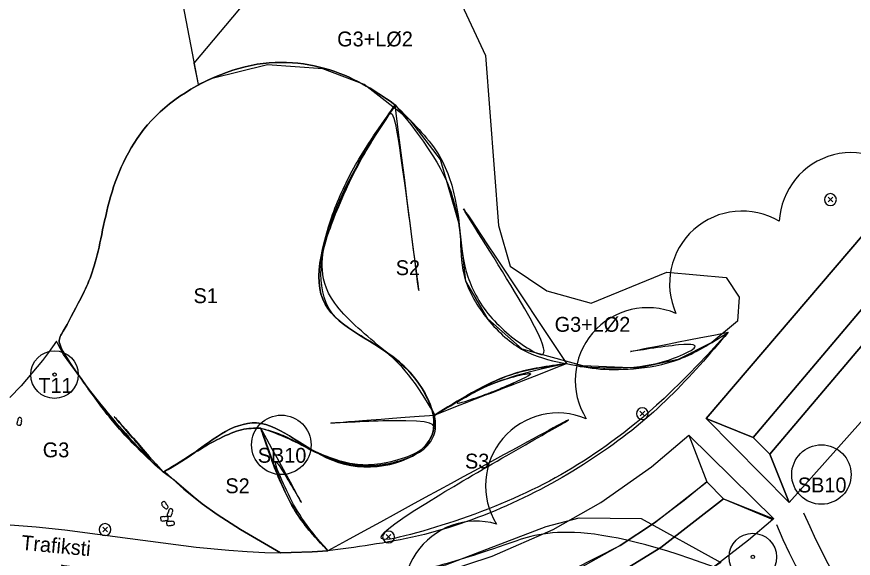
# Model space of a CAD drawing. Extents: x 0 to 512122, y 0 to 6212554.
# Drawn here: x 511431.1 to 511501.5, y 6211460.8 to 6211506.3 of the extents above; entities that cross this region are included whole.
import ezdxf

# ---------------------------------------------------------------- set-up
doc = ezdxf.new("R2010")
doc.units = 0
for name, color, linetype in [('_color plan_G3', 7, 'Continuous'), ('_lights', 7, 'Continuous'), ('_Marksten', 7, 'Continuous'), ('_Paths', 7, 'Continuous'), ('_S1_rabarber', 7, 'Continuous'), ('_S2_skovjorbær', 7, 'Continuous'), ('_S3_Mynte', 7, 'Continuous'), ('_Spredmingskorridor', 7, 'Continuous'), ('_Spredmingskorridor_hatch', 7, 'Continuous'), ('Clouds', 7, 'Continuous'), ('L40 jord udlagt muld og grøft', 7, 'Continuous'), ('Skel', 7, 'Continuous'), ('TV_U_AFM_Symbl_Gul', 7, 'Continuous'), ('TV_U_LYS_Mastenummer', 7, 'Continuous'), ('TV_U_LYS_Nyx330-Trafiksti-x2', 7, 'Continuous')]:
    doc.layers.add(name, color=color, linetype=linetype)

# ---------------------------------------------------------------- blocks, each defined once
blk = doc.blocks.new('SOLITAIRE TREES')
at = {"layer": 'Skel'}
for radius in [2, 0.141]:
    blk.add_circle((0, 0), radius, dxfattribs=at)

msp = doc.modelspace()

# ---------------------------------------------------------------- linework, layer by layer
at = {"layer": '_color plan_G3'}
msp.add_line((511446.415, 6211500.583), (511427.307, 6211601.517), dxfattribs=at)
at = {"layer": '_lights'}
for p, q in [((511499.408, 6211491.119), (511499.802, 6211490.725)), ((511499.806, 6211491.123), (511499.412, 6211490.729)), ((511483.575, 6211473.122), (511483.97, 6211472.728)), ((511483.973, 6211473.126), (511483.579, 6211472.732)), ((511438.364, 6211463.381), (511438.758, 6211462.987)), ((511438.762, 6211463.385), (511438.368, 6211462.991)), ((511462.223, 6211462.758), (511462.617, 6211462.363)), ((511462.621, 6211462.761), (511462.227, 6211462.367))]:
    msp.add_line(p, q, dxfattribs=at)
for centre, start, end in [((511499.605, 6211490.922), 315.56363, 315), ((511499.605, 6211490.922), 315, 315.56363), ((511483.772, 6211472.925), 315.56363, 315), ((511483.772, 6211472.925), 315, 315.56363), ((511438.561, 6211463.184), 315.56363, 315), ((511438.561, 6211463.184), 315, 315.56363), ((511462.42, 6211462.56), 315.56363, 315), ((511462.42, 6211462.56), 315, 315.56363)]:
    msp.add_arc(centre, 0.5, start, end, dxfattribs=at)
at = {"layer": '_Marksten'}
for points in [[(511431.425, 6211471.939), (511431.485, 6211472.018), (511431.516, 6211472.07), (511431.515, 6211472.155), (511431.534, 6211472.217), (511431.552, 6211472.28), (511431.531, 6211472.321), (511431.539, 6211472.366), (511431.55, 6211472.427), (511431.542, 6211472.483), (511431.514, 6211472.558), (511431.486, 6211472.577), (511431.458, 6211472.584), (511431.415, 6211472.594), (511431.34, 6211472.597), (511431.295, 6211472.576), (511431.272, 6211472.55), (511431.244, 6211472.505), (511431.219, 6211472.438), (511431.215, 6211472.362), (511431.202, 6211472.286), (511431.16, 6211472.229), (511431.164, 6211472.167), (511431.149, 6211472.121), (511431.144, 6211472.081), (511431.152, 6211472.002), (511431.186, 6211471.973), (511431.269, 6211471.951), (511431.33, 6211471.965)], [(511443.308, 6211465.398), (511443.325, 6211465.3), (511443.341, 6211465.242), (511443.404, 6211465.185), (511443.437, 6211465.129), (511443.47, 6211465.073), (511443.515, 6211465.06), (511443.542, 6211465.023), (511443.58, 6211464.974), (511443.626, 6211464.942), (511443.699, 6211464.91), (511443.733, 6211464.917), (511443.757, 6211464.933), (511443.793, 6211464.958), (511443.847, 6211465.012), (511443.862, 6211465.058), (511443.859, 6211465.092), (511443.845, 6211465.144), (511443.813, 6211465.207), (511443.761, 6211465.263), (511443.713, 6211465.324), (511443.701, 6211465.393), (511443.653, 6211465.433), (511443.63, 6211465.475), (511443.604, 6211465.507), (511443.541, 6211465.554), (511443.496, 6211465.549), (511443.423, 6211465.503), (511443.392, 6211465.449)], [(511444.052, 6211464.277), (511444.124, 6211464.346), (511444.163, 6211464.392), (511444.176, 6211464.476), (511444.204, 6211464.535), (511444.232, 6211464.593), (511444.218, 6211464.637), (511444.233, 6211464.68), (511444.253, 6211464.739), (511444.254, 6211464.795), (511444.239, 6211464.874), (511444.214, 6211464.898), (511444.188, 6211464.909), (511444.147, 6211464.925), (511444.073, 6211464.94), (511444.025, 6211464.927), (511443.999, 6211464.905), (511443.964, 6211464.865), (511443.929, 6211464.803), (511443.912, 6211464.728), (511443.888, 6211464.655), (511443.837, 6211464.606), (511443.83, 6211464.544), (511443.809, 6211464.501), (511443.797, 6211464.462), (511443.793, 6211464.383), (511443.822, 6211464.349), (511443.9, 6211464.314), (511443.963, 6211464.319)], [(511443.243, 6211463.95), (511443.335, 6211463.912), (511443.393, 6211463.895), (511443.475, 6211463.918), (511443.54, 6211463.916), (511443.605, 6211463.914), (511443.639, 6211463.945), (511443.685, 6211463.949), (511443.747, 6211463.954), (511443.799, 6211463.975), (511443.864, 6211464.021), (511443.876, 6211464.053), (511443.876, 6211464.082), (511443.874, 6211464.126), (511443.858, 6211464.2), (511443.826, 6211464.238), (511443.796, 6211464.253), (511443.745, 6211464.269), (511443.674, 6211464.276), (511443.599, 6211464.261), (511443.522, 6211464.254), (511443.457, 6211464.28), (511443.397, 6211464.261), (511443.35, 6211464.264), (511443.309, 6211464.258), (511443.235, 6211464.231), (511443.216, 6211464.19), (511443.216, 6211464.104), (511443.245, 6211464.049)], [(511443.762, 6211463.547), (511443.854, 6211463.509), (511443.912, 6211463.493), (511443.994, 6211463.515), (511444.059, 6211463.513), (511444.124, 6211463.511), (511444.158, 6211463.542), (511444.204, 6211463.546), (511444.266, 6211463.551), (511444.317, 6211463.573), (511444.383, 6211463.618), (511444.395, 6211463.65), (511444.394, 6211463.679), (511444.393, 6211463.723), (511444.376, 6211463.797), (511444.345, 6211463.835), (511444.314, 6211463.85), (511444.264, 6211463.866), (511444.193, 6211463.873), (511444.118, 6211463.858), (511444.041, 6211463.851), (511443.976, 6211463.878), (511443.916, 6211463.858), (511443.868, 6211463.861), (511443.828, 6211463.855), (511443.754, 6211463.828), (511443.734, 6211463.787), (511443.734, 6211463.701), (511443.764, 6211463.646)]]:
    msp.add_lwpolyline(points, close=True, dxfattribs=at)
at = {"layer": '_Paths'}
for points in [[(511619.187, 6211386.799), (511596.582, 6211393.479), (511585.389, 6211391.465), (511574.074, 6211393.08), (511564.353, 6211396.519), (511555.151, 6211400.37), (511543.395, 6211408.318), (511538.005, 6211417.069), (511534.527, 6211422.707), (511527.544, 6211428.597), (511520.899, 6211430.592), (511516.505, 6211433.059), (511513.01, 6211439.693), (511510.466, 6211444.112), (511507.781, 6211450.658), (511503.375, 6211454.994), (511500.203, 6211458.077), (511497.377, 6211464.569)], [(511614.911, 6211385.469), (511596.457, 6211390.915), (511585.439, 6211388.932), (511573.475, 6211390.64), (511563.453, 6211394.185), (511553.957, 6211398.16), (511541.549, 6211406.549), (511535.876, 6211415.757), (511532.609, 6211421.054), (511526.328, 6211426.352), (511519.916, 6211428.277), (511514.638, 6211431.24), (511510.82, 6211438.486), (511508.216, 6211443.009), (511505.662, 6211449.236), (511501.627, 6211453.206), (511498.108, 6211456.628), (511495.085, 6211463.571)]]:
    msp.add_open_spline(points, degree=3, dxfattribs=at)
at = {"layer": '_S1_rabarber'}
for points in [[(511462.989, 6211498.863), (511462.226, 6211499.418), (511458.709, 6211501.978), (511451.023, 6211503.141), (511442.323, 6211498.657), (511438.859, 6211491.961), (511437.944, 6211485.398), (511436.297, 6211482.152), (511434.723, 6211479.243), (511434.406, 6211478.815), (511436.593, 6211475.794)], [(511436.593, 6211475.794), (511434.406, 6211478.815), (511434.723, 6211479.243), (511436.297, 6211482.152), (511437.944, 6211485.398), (511438.859, 6211491.961), (511442.323, 6211498.657), (511451.023, 6211503.141), (511458.709, 6211501.978), (511462.226, 6211499.418), (511462.989, 6211498.863)], [(511443.449, 6211468.006), (511443.449, 6211468.006), (511445.663, 6211469.104), (511451.623, 6211474.122), (511458.055, 6211467.003), (511468.472, 6211469.925), (511463.799, 6211478.409), (511454.778, 6211481.205), (511458.363, 6211492.059), (511461.578, 6211496.788), (511462.989, 6211498.863)], [(511462.989, 6211498.863), (511461.578, 6211496.788), (511458.363, 6211492.059), (511454.778, 6211481.205), (511463.799, 6211478.409), (511468.472, 6211469.925), (511458.055, 6211467.003), (511451.623, 6211474.122), (511445.663, 6211469.104), (511443.449, 6211468.006), (511443.449, 6211468.006)], [(511436.593, 6211475.794), (511438.287, 6211473.464), (511441.968, 6211469.374), (511443.449, 6211468.006), (511436.593, 6211475.794), (511443.449, 6211468.006)], [(511443.449, 6211468.006), (511442.951, 6211468.457), (511441.095, 6211470.142), (511438.759, 6211472.727), (511437.147, 6211475.01), (511436.593, 6211475.794)]]:
    msp.add_open_spline(points, degree=3, dxfattribs=at)
at = {"layer": '_S2_skovjorbær'}
for points in [[(511443.578, 6211468.079), (511443.57, 6211468.074), (511445.195, 6211466.578), (511446.733, 6211465.339), (511447.983, 6211464.452), (511449.971, 6211463.191), (511453.338, 6211461.235), (511454.22, 6211461.241), (511455.977, 6211461.303), (511457.321, 6211461.397)], [(511457.321, 6211461.397), (511455.977, 6211461.303), (511454.22, 6211461.241), (511453.338, 6211461.235), (511449.971, 6211463.191), (511447.983, 6211464.452), (511446.733, 6211465.339), (511445.195, 6211466.578), (511443.57, 6211468.074), (511443.578, 6211468.079)]]:
    msp.add_lwpolyline(points, dxfattribs=at)
for points in [[(511466.301, 6211472.812), (511465.762, 6211474.059), (511464.786, 6211476.319), (511461.154, 6211478.953), (511457.036, 6211481.082), (511456.51, 6211485.204), (511457.34, 6211489.031), (511459.296, 6211493.505), (511461.652, 6211497.023), (511462.874, 6211498.746), (511462.968, 6211498.879)], [(511466.301, 6211472.812), (511464.386, 6211476.297), (511461.887, 6211478.346), (511457.205, 6211482.346), (511456.683, 6211485.477), (511457.088, 6211487.686), (511459.532, 6211493.557), (511462.685, 6211498.479), (511462.968, 6211498.879), (511466.301, 6211472.812), (511462.968, 6211498.879)], [(511466.301, 6211472.812), (511464.386, 6211476.297), (511461.887, 6211478.346), (511457.205, 6211482.346), (511456.683, 6211485.477), (511457.088, 6211487.686), (511459.532, 6211493.557), (511462.685, 6211498.479), (511462.968, 6211498.879), (511466.301, 6211472.812), (511462.968, 6211498.879)], [(511462.968, 6211498.879), (511466.855, 6211494.198), (511468.209, 6211490.046), (511468.441, 6211487.962), (511468.81, 6211484.464), (511470.824, 6211480.823), (511474.7, 6211477.831), (511477.381, 6211477.13), (511462.968, 6211498.879), (511477.381, 6211477.13)], [(511462.968, 6211498.879), (511466.855, 6211494.198), (511468.209, 6211490.046), (511468.441, 6211487.962), (511468.81, 6211484.464), (511470.824, 6211480.823), (511474.7, 6211477.831), (511477.381, 6211477.13), (511462.968, 6211498.879), (511477.381, 6211477.13)], [(511462.968, 6211498.879), (511464.432, 6211497.426), (511466.948, 6211494.929), (511468.175, 6211490.796), (511468.515, 6211487.502), (511468.519, 6211484.168), (511470.796, 6211480.478), (511473.933, 6211477.808), (511476.466, 6211477.31), (511477.381, 6211477.13)], [(511477.381, 6211477.13), (511472.658, 6211476.176), (511469.237, 6211474.575), (511466.301, 6211472.812), (511477.381, 6211477.13), (511466.301, 6211472.812)], [(511477.381, 6211477.13), (511472.658, 6211476.176), (511469.237, 6211474.575), (511466.301, 6211472.812), (511477.381, 6211477.13), (511466.301, 6211472.812)], [(511477.381, 6211477.13), (511475.777, 6211476.908), (511472.916, 6211476.513), (511469.309, 6211474.672), (511467.27, 6211473.411), (511466.301, 6211472.812)], [(511451.665, 6211471.703), (511451.131, 6211471.703), (511450.081, 6211471.703), (511448.275, 6211470.912), (511446.115, 6211469.703), (511444.498, 6211468.629), (511443.578, 6211468.079)], [(511443.578, 6211468.079), (511444.498, 6211468.629), (511446.115, 6211469.703), (511448.275, 6211470.912), (511450.081, 6211471.703), (511451.131, 6211471.703), (511451.665, 6211471.703)], [(511457.321, 6211461.397), (511456.525, 6211462.225), (511454.589, 6211464.237), (511452.992, 6211467.938), (511452.058, 6211470.587), (511451.665, 6211471.703)], [(511451.665, 6211471.703), (511452.058, 6211470.587), (511452.992, 6211467.938), (511454.589, 6211464.237), (511456.525, 6211462.225), (511457.321, 6211461.397)]]:
    msp.add_open_spline(points, degree=3, dxfattribs=at)
at = {"layer": '_S3_Mynte'}
for points in [[(511491.009, 6211479.767), (511486.059, 6211474.315), (511480.552, 6211469.782), (511473.336, 6211465.655), (511463.75, 6211462.391), (511457.319, 6211461.406), (511491.009, 6211479.767), (511457.319, 6211461.406)], [(511491.009, 6211479.767), (511489.412, 6211477.898), (511486.269, 6211474.218), (511480.349, 6211469.375), (511472.908, 6211465.158), (511464.984, 6211462.359), (511459.474, 6211461.674), (511457.319, 6211461.406)], [(511477.381, 6211477.13), (511479.435, 6211476.759), (511482.787, 6211476.687), (511486.264, 6211477.305), (511491.009, 6211479.767), (511477.381, 6211477.13), (511491.009, 6211479.767)], [(511477.381, 6211477.13), (511478.064, 6211476.989), (511479.843, 6211476.621), (511482.848, 6211476.601), (511486.939, 6211477.214), (511489.479, 6211478.807), (511491.009, 6211479.767)], [(511466.301, 6211472.812), (511466.965, 6211473.194), (511469.648, 6211474.776), (511471.548, 6211475.747), (511477.381, 6211477.13), (511466.301, 6211472.812), (511477.381, 6211477.13)], [(511466.301, 6211472.812), (511466.523, 6211472.939), (511467.646, 6211473.582), (511469.348, 6211474.634), (511472.665, 6211476.422), (511475.379, 6211476.83), (511477.381, 6211477.13)], [(511451.665, 6211471.703), (511452.398, 6211471.514), (511454.238, 6211470.759), (511455.862, 6211469.888), (511458.09, 6211468.978), (511459.786, 6211468.601), (511461.656, 6211468.63), (511464.239, 6211469.297), (511465.631, 6211470.154), (511466.356, 6211471.576), (511466.301, 6211472.812), (511451.665, 6211471.703), (511466.301, 6211472.812)], [(511451.665, 6211471.703), (511451.91, 6211471.644), (511452.801, 6211471.429), (511454.215, 6211470.815), (511456.006, 6211469.759), (511457.86, 6211468.998), (511459.82, 6211468.513), (511461.934, 6211468.585), (511463.938, 6211469.09), (511465.73, 6211470.011), (511466.49, 6211471.448), (511466.358, 6211472.397), (511466.301, 6211472.812)], [(511457.319, 6211461.406), (511455.374, 6211463.574), (511453.813, 6211466.156), (511451.665, 6211471.703), (511457.319, 6211461.406), (511451.665, 6211471.703)], [(511457.319, 6211461.406), (511456.64, 6211462.104), (511455.256, 6211463.525), (511453.257, 6211466.984), (511452.3, 6211469.821), (511451.665, 6211471.703)]]:
    msp.add_open_spline(points, degree=3, dxfattribs=at)
at = {"layer": '_Spredmingskorridor'}
msp.add_lwpolyline([(511430.566, 6211463.587), (511432.775, 6211463.422), (511435.179, 6211463.168), (511440.672, 6211462.441), (511446.241, 6211461.704), (511448.986, 6211461.437), (511450.514, 6211461.329), (511452.005, 6211461.264), (511453.338, 6211461.235), (511451.655, 6211462.213), (511449.971, 6211463.191), (511447.983, 6211464.452), (511446.733, 6211465.339), (511445.964, 6211465.959), (511444.383, 6211467.326), (511443.449, 6211468.006), (511441.821, 6211469.544), (511439.763, 6211471.673), (511438.112, 6211473.703), (511436.593, 6211475.794), (511435.075, 6211477.885), (511434.56, 6211478.847), (511434.465, 6211479.025), (511434.147, 6211478.548), (511433.814, 6211478.075), (511433.562, 6211477.733), (511433.297, 6211477.381), (511431.505, 6211475.271), (511430.537, 6211474.276)], dxfattribs=at)
msp.add_open_spline([(511492.266, 6211459.065), (511479.169, 6211464.34), (511471.697, 6211461.691), (511466.477, 6211459.966), (511460.05, 6211458.675), (511492.266, 6211459.065), (511460.05, 6211458.675)], degree=3, dxfattribs=at)
at = {"layer": '_Spredmingskorridor_hatch'}
msp.add_lwpolyline([(511434.899, 6211460.179), (511449.469, 6211458.386), (511457.611, 6211458.367), (511460.142, 6211458.361), (511460.05, 6211458.675), (511467.249, 6211460.221), (511475.684, 6211463.431), (511478.446, 6211464.171), (511483.675, 6211464.122), (511490.383, 6211460.419), (511481.456, 6211454.685), (511471.837, 6211450.715), (511467.654, 6211449.509), (511465.235, 6211448.962), (511459.073, 6211449.517), (511452.451, 6211450.939), (511445.522, 6211453.191), (511442.233, 6211454.953), (511440.542, 6211456.402), (511439.749, 6211457.341), (511438.957, 6211458.281), (511437.872, 6211458.962), (511437.365, 6211459.28), (511435.882, 6211459.843)], close=True, dxfattribs=at)
at = {"layer": 'Clouds'}
for centre, start, end in [((511501.384, 6211488.771), 31.95943, 176.95943), ((511492.17, 6211483.854), 59.21389, 204.21389), ((511484.229, 6211475.735), 67.05793, 212.05793), ((511476.679, 6211466.88), 67.03365, 212.03365), ((511469.797, 6211457.789), 73.7112, 218.7112)]:
    msp.add_arc(centre, 6.1, start, end, dxfattribs=at)
at = {"layer": 'L40 jord udlagt muld og grøft'}
for points in [[(511493.098, 6211470.93), (511516.255, 6211498.237), (511514.47, 6211502.135), (511489.133, 6211472.51), (511493.098, 6211470.93)], [(511490.613, 6211465.77), (511494.758, 6211464.022), (511492.715, 6211462.301), (511488.249, 6211458.832), (511478.239, 6211453.123), (511472.318, 6211450.824), (511467.621, 6211449.487), (511459.919, 6211448.147), (511453.669, 6211447.799), (511451.752, 6211448.284), (511453.654, 6211451.799), (511457.679, 6211451.96), (511464.172, 6211452.828), (511469.835, 6211454.235), (511476.131, 6211456.564), (511480.685, 6211458.81), (511485.335, 6211461.675), (511490.613, 6211465.77)]]:
    msp.add_lwpolyline(points, dxfattribs=at)
for points in [[(511489.133, 6211472.51), (511514.47, 6211502.135), (511516.255, 6211498.237), (511493.098, 6211470.93)], [(511516.255, 6211498.237), (511517.74, 6211496.898), (511494.504, 6211469.514), (511493.094, 6211470.934)], [(511517.74, 6211496.898), (511522.453, 6211494.939), (511496.129, 6211465.466), (511494.504, 6211469.514)], [(511489.133, 6211472.51), (511493.094, 6211470.934), (511494.504, 6211469.514), (511496.132, 6211465.468)], [(511452.089, 6211457.757), (511455.883, 6211457.797), (511458.754, 6211458.017), (511462.669, 6211458.587), (511466.946, 6211459.576), (511471.14, 6211460.94), (511476.281, 6211463.197), (511480.272, 6211465.454), (511484.554, 6211468.459), (511487.69, 6211471.125), (511489.2, 6211467.192), (511487.305, 6211465.616), (511484.793, 6211463.737), (511481.902, 6211461.832), (511478.062, 6211459.686), (511474.061, 6211457.856), (511469.926, 6211456.355), (511467.817, 6211455.732), (511464.514, 6211454.937), (511461.957, 6211454.47), (511459.08, 6211454.092), (511455.823, 6211453.851), (511453.649, 6211453.799)], [(511487.69, 6211471.125), (511489.2, 6211467.192), (511490.613, 6211465.77), (511494.83, 6211464.097)], [(511489.2, 6211467.192), (511490.613, 6211465.77), (511485.335, 6211461.675), (511480.685, 6211458.81), (511476.131, 6211456.564), (511469.835, 6211454.235), (511464.172, 6211452.828), (511457.679, 6211451.96), (511453.654, 6211451.799), (511453.649, 6211453.799), (511459.08, 6211454.092), (511466.165, 6211455.334), (511474.061, 6211457.856), (511481.902, 6211461.832), (511484.793, 6211463.737)], [(511490.613, 6211465.77), (511494.758, 6211464.022), (511492.715, 6211462.301), (511488.249, 6211458.832), (511478.239, 6211453.123), (511472.318, 6211450.824), (511467.621, 6211449.487), (511459.919, 6211448.147), (511453.669, 6211447.799), (511451.752, 6211448.284), (511453.654, 6211451.799), (511457.679, 6211451.96), (511464.172, 6211452.828), (511469.835, 6211454.235), (511476.131, 6211456.564), (511480.685, 6211458.81), (511485.335, 6211461.675)]]:
    msp.add_lwpolyline(points, close=True, dxfattribs=at)
at = {"layer": 'TV_U_LYS_Mastenummer'}
for centre in [(511453.395, 6211470.298), (511453.395, 6211470.298), (511498.846, 6211467.803)]:
    msp.add_circle(centre, 2.5, dxfattribs=at)
at = {"layer": 'TV_U_LYS_Nyx330-Trafiksti-x2'}
msp.add_lwpolyline([(511468.375, 6211507.746), (511470.563, 6211503.026), (511471.683, 6211488.737), (511472.662, 6211485.324), (511475.751, 6211483.257), (511479.476, 6211482.226), (511485.84, 6211484.813), (511490.823, 6211484.374), (511491.914, 6211482.723), (511491.914, 6211482.723), (511491.781, 6211480.688), (511489.611, 6211478.904), (511486.778, 6211477.484), (511483.431, 6211476.742), (511478.768, 6211476.947), (511473.669, 6211478.339), (511470.759, 6211480.901), (511468.927, 6211484.066), (511468.376, 6211488.77), (511466.797, 6211494.304), (511464.28, 6211497.556), (511460.369, 6211500.594), (511456.891, 6211501.902), (511452.222, 6211502.257), (511447.585, 6211501.113), (511446.415, 6211500.583), (511446.071, 6211502.399), (511450.928, 6211508.217)], dxfattribs=at)

# ---------------------------------------------------------------- block references
at = {"layer": 'Skel'}
for p in [(511434.309, 6211476.207), (511493.074, 6211460.876)]:
    msp.add_blockref('SOLITAIRE TREES', p, dxfattribs=at)

# ---------------------------------------------------------------- texts
at = {"layer": 'TV_U_AFM_Symbl_Gul'}
for s, p in [('G3+LØ2', (511458.096, 6211503.798)), ('S2', (511463.025, 6211484.569)), ('S1', (511446.007, 6211482.215)), ('G3+LØ2', (511476.396, 6211479.807)), ('T11', (511432.952, 6211474.672)), ('G3', (511433.319, 6211469.255)), ('SB10', (511451.412, 6211468.797)), ('S3', (511468.851, 6211468.31)), ('S2', (511448.69, 6211466.237)), ('SB10', (511496.864, 6211466.302))]:
    msp.add_text(s, height=1.25, dxfattribs=at).set_placement(p)
msp.add_text('Trafiksti', height=1.25, rotation=354.65162, dxfattribs=at).set_placement((511431.468, 6211461.482))

doc.saveas('drawing.dxf')
